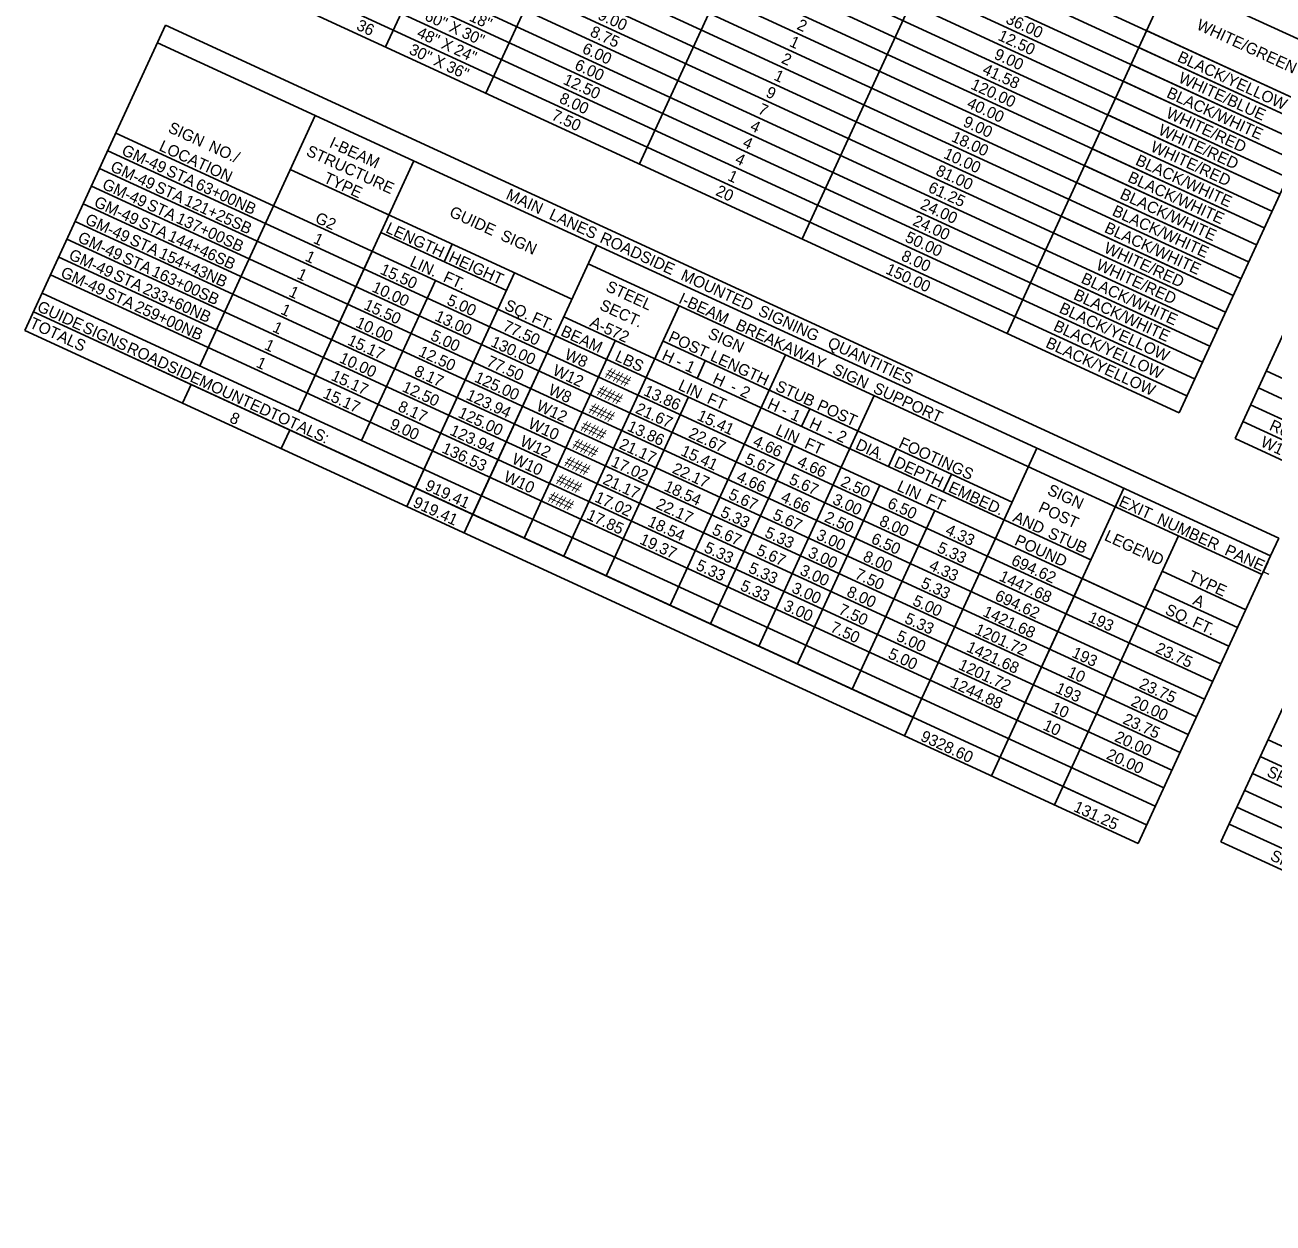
# Model space of a CAD drawing. Extents: x 627405 to 651306, y 367647 to 373430.
# Drawn here: x 649975 to 650630, y 372391 to 373020 of the extents above; entities that cross this region are included whole.
import ezdxf

# ---------------------------------------------------------------- set-up
doc = ezdxf.new("R2010")
doc.units = 0
doc.layers.add('Default', color=7, linetype='Continuous')
doc.layers.add('R_Dimension', color=7, linetype='Continuous')

msp = doc.modelspace()

# ---------------------------------------------------------------- linework, layer by layer
at = {"layer": 'Default'}
for p, q in [((650164.52, 373008.63), (650327.74, 373362.83)), ((650217.21, 372984.35), (650380.43, 373338.55)), ((650297.79, 372947.21), (650461.01, 373301.42)), ((650383.24, 372907.84), (650546.46, 373262.04)), ((650150.38, 373240.04), (650666.63, 373002.15)), ((650138.14, 373213.48), (650654.39, 372975.59)), ((650490.83, 372858.26), (650654.05, 373212.46)), ((650134.06, 373204.62), (650650.31, 372966.73)), ((650129.98, 373195.77), (650646.23, 372957.88)), ((650581.15, 372816.64), (650754.16, 373192.09)), ((650125.9, 373186.91), (650642.15, 372949.02)), ((650121.82, 373178.06), (650638.07, 372940.17)), ((650117.74, 373169.2), (650633.99, 372931.31)), ((650113.66, 373160.35), (650629.91, 372922.46)), ((650109.58, 373151.49), (650625.83, 372913.6)), ((650105.5, 373142.64), (650621.75, 372904.75)), ((650101.42, 373133.78), (650617.67, 372895.89)), ((650097.34, 373124.93), (650613.59, 372887.04)), ((650093.26, 373116.07), (650609.51, 372878.18)), ((650089.18, 373107.22), (650605.43, 372869.33)), ((650610.54, 372803.1), (650751.11, 373108.15)), ((650085.1, 373098.36), (650601.35, 372860.47)), ((650081.02, 373089.51), (650597.27, 372851.62)), ((650077.14, 373081.1), (650593.39, 372843.2)), ((650073.06, 373072.24), (650589.31, 372834.35)), ((650068.98, 373063.39), (650585.23, 372825.49)), ((650064.9, 373054.53), (650490.83, 372858.26)), ((649975.17, 372859.82), (650049.03, 373020.09)), ((650049.03, 373020.09), (650633.46, 372750.78)), ((650564.07, 373017.21), (650654.39, 372975.59)), ((650044.75, 373010.8), (650629.18, 372741.48)), ((650044.75, 373010.8), (650629.18, 372741.48)), ((650559.99, 373008.35), (650650.31, 372966.73)), ((650555.91, 372999.5), (650646.23, 372957.88)), ((650551.83, 372990.64), (650642.15, 372949.02)), ((650547.75, 372981.79), (650638.07, 372940.17)), ((650066.94, 372841.15), (650127.54, 372972.64)), ((650543.67, 372972.93), (650633.99, 372931.31)), ((650022.91, 372963.42), (650607.35, 372694.11)), ((650539.59, 372964.08), (650629.91, 372922.46)), ((650018.63, 372954.12), (650603.06, 372684.81)), ((650535.51, 372955.22), (650625.83, 372913.6)), ((650118.75, 372817.28), (650179.34, 372948.77)), ((650014.35, 372944.83), (650598.78, 372675.51)), ((650114.48, 372944.31), (650262.36, 372876.16)), ((650531.43, 372946.37), (650621.75, 372904.75)), ((650010.06, 372935.53), (650594.5, 372666.22)), ((650527.35, 372937.51), (650617.67, 372895.89)), ((650005.78, 372926.23), (650590.21, 372656.92)), ((650001.49, 372916.93), (650585.93, 372647.62)), ((650519.19, 372919.8), (650609.51, 372878.18)), ((649997.21, 372907.64), (650581.64, 372638.32)), ((650162, 372911.14), (650227.97, 372880.74)), ((650118.75, 372817.28), (650157.51, 372901.4)), ((650195.21, 372895.84), (650199.49, 372905.14)), ((650205.85, 372753.52), (650275.42, 372904.5)), ((649992.92, 372898.34), (650577.36, 372629.03)), ((650270.93, 372894.76), (650624.69, 372731.74)), ((649988.64, 372889.04), (650573.07, 372619.73)), ((650223.48, 372871), (650232.26, 372890.04)), ((650506.94, 372893.24), (650597.27, 372851.62)), ((650151.95, 372801.97), (650190.72, 372886.1)), ((649984.15, 372879.3), (650118.75, 372817.28)), ((649979.66, 372869.56), (650441.45, 372656.76)), ((649979.66, 372869.56), (650210.34, 372763.26)), ((650175.74, 372767.4), (650223.48, 372871)), ((650180.23, 372777.14), (650223.48, 372871)), ((650258.15, 372741.23), (650318.75, 372872.73)), ((650258.08, 372866.87), (650534.8, 372739.35)), ((649975.17, 372859.82), (650559.61, 372590.51)), ((650210.34, 372763.26), (650253.59, 372857.13)), ((650490.83, 372858.26), (650581.15, 372816.64)), ((650237.34, 372750.82), (650285.09, 372854.42)), ((650310.18, 372854.13), (650493.48, 372769.66)), ((650313.94, 372715.52), (650374.54, 372847.02)), ((650328.03, 372834.63), (650332.32, 372843.93)), ((650626.86, 372838.52), (651132.93, 372605.32)), ((650057.97, 372821.67), (650062.46, 372831.41)), ((650622.78, 372829.66), (651128.85, 372596.46)), ((650280.29, 372731.03), (650323.54, 372824.89)), ((650360.43, 372694.1), (650421.02, 372825.6)), ((650118.75, 372817.28), (650568.58, 372609.99)), ((650382.93, 372809.33), (650387.22, 372818.63)), ((650618.7, 372820.81), (651124.77, 372587.61)), ((650614.62, 372811.95), (651120.69, 372578.75)), ((650109.77, 372797.79), (650114.26, 372807.54)), ((650109.77, 372797.79), (650114.26, 372807.54)), ((650610.54, 372803.1), (650839, 372697.82)), ((650335.19, 372705.73), (650378.45, 372799.59)), ((650428.54, 372788.32), (650432.82, 372797.61)), ((650484.71, 372750.62), (650506.54, 372798)), ((650457.32, 372775.06), (650461.6, 372784.35)), ((650380.8, 372684.71), (650424.05, 372778.58)), ((650482.57, 372626.01), (650552.14, 372776.99)), ((650210.34, 372763.26), (650564.1, 372600.25)), ((650409.57, 372671.45), (650452.83, 372765.31)), ((650436.96, 372647.02), (650484.71, 372750.62)), ((650436.96, 372647.02), (650484.71, 372750.62)), ((650563.52, 372714.31), (650580.86, 372751.94)), ((650629.18, 372741.48), (650633.46, 372750.78)), ((650559.61, 372590.51), (650629.18, 372741.48)), ((650572.29, 372733.35), (650616.12, 372713.15)), ((650603.15, 372591.37), (650669.05, 372734.38)), ((650482.57, 372626.01), (650530.31, 372729.61)), ((650530.31, 372729.61), (650607.35, 372694.11)), ((650568, 372724.05), (650611.84, 372703.85)), ((650515.77, 372610.7), (650563.52, 372714.31)), ((650515.77, 372610.7), (650563.52, 372714.31)), ((650627.84, 372644.95), (651062.18, 372444.8)), ((650487.06, 372635.75), (650520.26, 372620.44)), ((650623.76, 372636.09), (651058.1, 372435.94)), ((650619.68, 372627.24), (651054.02, 372427.09)), ((650520.26, 372620.44), (650564.1, 372600.25)), ((650615.6, 372618.38), (651049.94, 372418.23)), ((650611.52, 372609.53), (651045.86, 372409.38)), ((650607.44, 372600.67), (651041.78, 372400.52)), ((650603.15, 372591.37), (651037.49, 372391.23))]:
    msp.add_line(p, q, dxfattribs=at)
at = {"layer": 'R_Dimension'}
msp.add_line((650049.03, 373020.09), (650049.03, 373020.09), dxfattribs=at)

# ---------------------------------------------------------------- texts
at = {"layer": 'Default'}
for s, p in [('60"', (650184.54, 373022.94)), (' 18"', (650205.95, 373023.54)), ('9.00', (650275.44, 373023.45)), ('36.00', (650489.66, 373021.36)), ('36', (650148.72, 373017.97)), (' X', (650195.31, 373017.97)), (' 30"', (650201.97, 373014.9)), ('8.75', (650271.4, 373014.58)), ('2', (650380.02, 373018.2)), ('WHITE/GREEN', (650589.81, 373018.15)), ('48"', (650180.46, 373014.08)), (' X', (650191.23, 373009.12)), ('1', (650376.08, 373009.28)), ('12.50', (650485.58, 373012.5)), ('30"', (650176.38, 373005.23)), (' 24"', (650197.89, 373006.05)), ('6.00', (650267.28, 373005.74)), ('9.00', (650483.54, 373002.7)), ('BLACK/YELLOW', (650579.76, 373001.31)), (' X', (650187.15, 373000.26)), (' 36"', (650193.81, 372997.19)), ('6.00', (650263.3, 372997.11)), ('2', (650371.86, 373000.49)), ('41.58', (650477.4, 372994.8)), ('12.50', (650257.28, 372989.42)), ('1', (650367.91, 372991.57)), ('WHITE/BLUE', (650580.32, 372990.32)), ('9', (650363.69, 372982.79)), ('120.00', (650471.29, 372986.88)), ('BLACK/WHITE', (650574.1, 372982.45)), ('8.00', (650255.24, 372979.62)), ('7', (650359.59, 372973.94)), ('40.00', (650469.25, 372977.08)), ('7.50', (650251.16, 372970.76)), ('WHITE/RED', (650573.81, 372971.84)), ('SIGN', (650049.84, 372964.14)), ('4', (650355.46, 372965.11)), ('9.00', (650467.22, 372967.28)), ('WHITE/RED', (650569.73, 372962.99)), ('LOCATION', (650045.11, 372954.52)), (' NO./', (650069.03, 372955.3)), ('I-BEAM', (650134.49, 372956.23)), ('4', (650351.48, 372956.47)), ('18.00', (650461.09, 372959.37)), ('WHITE/RED', (650565.65, 372954.13)), ('GM-49', (650025.43, 372952.31)), ('STRU', (650122.33, 372951.92)), ('10.00', (650457.01, 372950.52)), ('GM-49', (650019.52, 372943.76)), ('CTURE', (650142.16, 372942.79)), ('4', (650347.51, 372947.84)), ('81.00', (650452.93, 372941.66)), ('BLACK/WHITE', (650557.77, 372947.03)), (' STA', (650046.8, 372942.46)), ('TYPE', (650131.49, 372937.79)), ('1', (650343.64, 372938.89)), ('BLACK/WHITE', (650553.69, 372938.17)), ('GM-49', (650015.24, 372934.47)), (' STA', (650040.89, 372933.92)), (' 63+00NB', (650062.22, 372935.36)), ('MAIN', (650227.22, 372929.05)), ('20', (650337.36, 372931.04)), ('61.25', (650448.9, 372932.79)), ('BLACK/WHITE', (650549.61, 372929.32)), ('GM-49', (650010.95, 372925.17)), (' STA', (650036.6, 372924.62)), (' 121+25SB', (650056.31, 372926.81)), ('24.00', (650444.77, 372923.95)), ('GM-49', (650006.25, 372916.06)), (' 137+00SB', (650052.02, 372917.51)), ('G2', (650127.04, 372916.76)), (' GUIDE', (650195.48, 372920.86)), (' LANES', (650247.9, 372919.52)), ('24.00', (650440.79, 372915.32)), ('BLACK/WHITE', (650545.53, 372920.46)), (' STA', (650032.32, 372915.32)), ('LENGTH', (650164.1, 372911.49)), ('BLACK/WHITE', (650541.45, 372911.61)), ('GM-49', (650002.38, 372906.57)), (' STA', (650027.62, 372906.21)), (' 144+46SB', (650047.74, 372908.22)), ('1', (650126.09, 372905.93)), (' SIGN', (650222.34, 372908.48)), (' ROADSIDE', (650274.51, 372907.25)), ('50.00', (650436.81, 372906.68)), ('GM-49', (649997.68, 372897.47)), (' STA', (650023.75, 372896.73)), (' 154+43NB', (650043.04, 372899.11)), ('1', (650121.8, 372896.63)), ('HEIGHT', (650197.16, 372896.26)), ('8.00', (650434.78, 372896.89)), ('WHITE/RED', (650541.17, 372901)), ('15.50', (650161.17, 372889.76)), ('LIN.', (650176.77, 372893.84)), ('150.00', (650426.61, 372889.92)), ('WHITE/RED', (650537.09, 372892.15)), ('GM-49', (649993.4, 372888.17)), (' STA', (650019.05, 372887.62)), (' 163+00SB', (650039.17, 372889.62)), ('1', (650117.52, 372887.33)), (' FT.', (650192.27, 372886.7)), (' MOUNTED', (650317.01, 372887.67)), ('BLACK/WHITE', (650529.21, 372885.04)), (' STA', (650014.77, 372878.32)), (' 233+60NB', (650034.47, 372880.51)), ('1', (650113.23, 372878.04)), ('10.00', (650156.89, 372880.46)), ('STEEL', (650279.68, 372880.78)), ('BLACK/WHITE', (650525.23, 372876.41)), ('GUIDE', (649981.05, 372870.24)), (' 259+00NB', (650030.19, 372871.22)), ('15.50', (650152.6, 372871.17)), ('5.00', (650196.2, 372873.62)), ('SQ.', (650226.39, 372870.98)), ('SECT.', (650276.39, 372871.02)), ('I-BEAM', (650317.91, 372874.43)), ('BLACK/', (650517.69, 372869.42)), ('1', (650108.95, 372868.74)), ('13.00', (650189.87, 372865.26)), (' FT.', (650238.73, 372865.29)), (' SIGNING', (650357.61, 372868.96)), ('TOTALS', (649977.05, 372861.56)), (' SIGNS', (650002.81, 372860.21)), ('1', (650104.66, 372859.44)), ('10.00', (650148.32, 372861.87)), ('77.50', (650225.59, 372860.08)), ('BEAM', (650255.99, 372857.34)), ('A-572', (650271.25, 372862.12)), (' BREAKAWAY', (650345.77, 372861.59)), ('BLACK/YELLOW', (650514.68, 372860.07)), (' YELLOW', (650541.9, 372858.26)), ('1', (650100.38, 372850.14)), ('15.17', (650144.02, 372852.58)), ('5.00', (650187.63, 372855.02)), ('130.00', (650219.26, 372851.72)), ('POST', (650312.46, 372854.4)), ('SIGN', (650333.27, 372856.08)), (' QUANTITIES', (650394.04, 372852.17)), ('BLACK/YELLOW', (650510.6, 372851.21)), (' ROADSIDE', (650026.11, 372849.48)), ('12.50', (650181.3, 372846.67)), ('W8', (650258.02, 372845.13)), ('LBS', (650284.48, 372844.21)), ('H', (650309.12, 372844.67)), (' LENGTH', (650332.49, 372845.17)), ('1', (650096.09, 372840.84)), ('10.00', (650139.75, 372843.27)), ('77.50', (650217.02, 372841.48)), ('W12', (650251.72, 372836.76)), (' -', (650314.28, 372842.29)), (' 1', (650319.3, 372839.97)), (' SIGN', (650396.57, 372838.19)), (' MOUNTED', (650063.99, 372832.02)), ('15.17', (650135.45, 372833.98)), ('8.17', (650179.05, 372836.44)), ('125.00', (650210.69, 372833.13)), ('###', (650279.3, 372835.33)), ('H', (650335.79, 372832.37)), ('15.17', (650131.16, 372824.69)), ('12.50', (650172.73, 372828.07)), ('W8', (650249.45, 372826.54)), ('###', (650275.01, 372826.03)), ('13.86', (650299.5, 372826.02)), ('LIN', (650317.66, 372828.92)), ('  -', (650340.96, 372830)), (' 2', (650348.17, 372826.67)), ('STUB', (650368.7, 372828.48)), (' SUPPORT', (650417.95, 372828.34)), ('8.17', (650170.48, 372817.84)), ('123.94', (650206.35, 372823.85)), ('W12', (650243.16, 372818.17)), (' FT', (650330.8, 372822.87)), ('H', (650364.46, 372819.16)), (' POST', (650388.49, 372819.36)), ('8', (650082.1, 372811.87)), (' TOTALS:', (650100.76, 372815.08)), ('125.00', (650202.12, 372814.53)), ('###', (650270.73, 372816.73)), ('21.67', (650295.23, 372816.71)), ('15.41', (650327.58, 372813.08)), (' -', (650369.63, 372816.79)), (' 1', (650374.65, 372814.47)), ('9.00', (650166.21, 372808.54)), ('123.94', (650197.78, 372805.26)), ('W10', (650238.86, 372808.88)), ('###', (650266.44, 372807.43)), ('13.86', (650290.93, 372807.42)), ('LIN', (650368.8, 372805.36)), ('H', (650386.49, 372809.01)), ('R6-1R', (650628.05, 372807.83)), ('W12', (650234.59, 372799.57)), ('###', (650262.16, 372798.14)), ('21.17', (650286.66, 372798.12)), ('22.67', (650323.12, 372803.86)), ('4.66', (650356.89, 372799.57)), (' FT', (650381.94, 372799.3)), ('  -', (650391.65, 372806.64)), (' 2', (650398.87, 372803.31)), ('DIA.', (650410.74, 372797.84)), ('FOOTINGS', (650433.43, 372798.65)), ('W1-8L', (650623.44, 372799.21)), ('136.53', (650193.62, 372795.91)), ('W10', (650230.29, 372790.28)), ('15.41', (650319.01, 372794.49)), ('###', (650257.87, 372788.84)), ('17.02', (650282.41, 372788.81)), ('22.17', (650314.55, 372785.27)), ('5.67', (650352.62, 372790.27)), ('4.66', (650380.14, 372788.86)), ('DEPTH', (650430.95, 372788.53)), ('W10', (650226, 372780.98)), ('###', (650253.59, 372779.54)), ('21.17', (650278.09, 372779.52)), ('4.66', (650348.32, 372780.98)), ('5.67', (650375.86, 372779.56)), ('2.50', (650402.96, 372778.34)), ('919.41', (650184.73, 372776.38)), ('18.54', (650310.23, 372775.99)), ('5.67', (650344.05, 372771.67)), ('LIN', (650432.55, 372775.98)), ('EMBED.', (650459.49, 372775.38)), ('SIGN', (650511.48, 372773.96)), ('919.41', (650178.42, 372767.48)), ('###', (650249.31, 372770.24)), ('17.02', (650273.84, 372770.21)), ('22.17', (650305.99, 372766.67)), ('4.66', (650371.57, 372770.27)), ('3.00', (650398.68, 372769.04)), ('6.50', (650427.54, 372767.02)), (' FT', (650445.7, 372769.92)), ('POST', (650506.77, 372764.86)), ('EXIT', (650549.04, 372767.93)), ('17.85', (650269.58, 372760.9)), ('5.33', (650339.84, 372762.34)), ('5.67', (650367.29, 372760.96)), ('2.50', (650394.4, 372759.75)), ('AND', (650493.34, 372759.78)), (' NUMBER', (650566.99, 372759.65)), ('18.54', (650301.66, 372757.39)), ('5.67', (650335.48, 372753.08)), ('5.33', (650363.09, 372751.63)), ('8.00', (650423.25, 372757.72)), ('4.33', (650457.93, 372753.01)), ('19.37', (650297.42, 372748.07)), ('3.00', (650390.11, 372750.45)), ('6.50', (650418.97, 372748.42)), ('POUND', (650494.29, 372747.53)), (' STUB', (650509.67, 372752.25)), ('LEGEND', (650541.43, 372749.9)), ('5.33', (650331.27, 372743.74)), ('5.67', (650358.73, 372742.37)), ('3.00', (650385.83, 372741.15)), ('8.00', (650414.68, 372739.12)), ('5.33', (650453.64, 372743.72)), (' PANEL', (650602.55, 372743.27)), ('5.33', (650326.99, 372734.45)), ('5.33', (650354.52, 372733.03)), ('3.00', (650381.54, 372731.85)), ('4.33', (650449.36, 372734.42)), ('694.62', (650492.53, 372737.07)), ('7.50', (650410.4, 372729.83)), ('5.33', (650445.07, 372725.12)), ('1447.68', (650486.17, 372728.73)), ('TYPE', (650585.32, 372728.67)), ('5.33', (650350.23, 372723.74)), ('3.00', (650377.26, 372722.55)), ('8.00', (650406.12, 372720.53)), ('3.00', (650372.97, 372713.26)), ('5.00', (650440.73, 372715.85)), ('694.62', (650483.96, 372718.47)), ('A', (650587.85, 372716.23)), ('7.50', (650401.83, 372711.23)), ('5.33', (650436.51, 372706.52)), ('1421.68', (650477.6, 372710.13)), ('193', (650532.92, 372707.18)), ('SQ.', (650573.29, 372711.13)), ('7.50', (650397.55, 372701.93)), ('1201.72', (650473.35, 372700.82)), (' FT.', (650585.63, 372705.44)), ('5.00', (650432.16, 372697.26)), ('5.00', (650427.87, 372687.96)), ('1421.68', (650469.04, 372691.53)), ('193', (650524.36, 372688.59)), ('23.75', (650568.25, 372690.91)), ('1201.72', (650464.78, 372682.22)), ('10', (650522.05, 372678.38)), ('1244.88', (650460.47, 372672.94)), ('193', (650515.79, 372669.99)), ('23.75', (650559.68, 372672.31)), ('20.00', (650555.35, 372663.03)), ('10', (650513.48, 372659.78)), ('23.75', (650551.11, 372653.71)), ('10', (650509.2, 372650.48)), ('9328.60', (650444.92, 372644.68)), ('20.00', (650546.78, 372644.44)), ('20.00', (650542.5, 372635.14)), ('SP,', (650626.73, 372626.05)), ('131.25', (650525.26, 372607.66)), ('SP', (650628.51, 372582.02))]:
    msp.add_text(s, height=6, rotation=335.25934, dxfattribs=at).set_placement(p)

doc.saveas('drawing.dxf')
